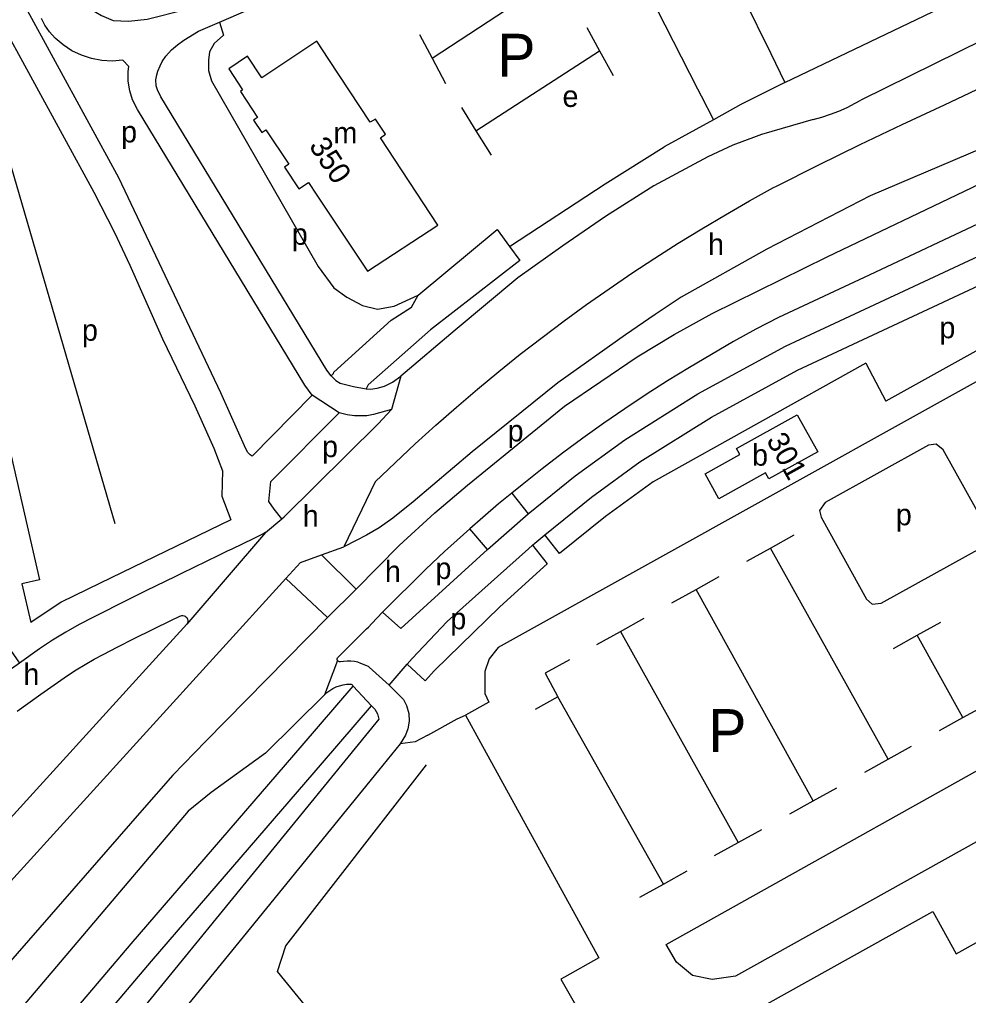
# Model space of a CAD drawing. Extents: x 155696 to 157795, y 382328 to 384028.
# Drawn here: x 157377.7 to 157554.8, y 382850.6 to 383032.8 of the extents above; entities that cross this region are included whole.
import ezdxf

# ---------------------------------------------------------------- set-up
doc = ezdxf.new("R2010")
doc.units = 0
for name, color, linetype in [('BLT_Basislijn', 7, 'Continuous'), ('BLT_Bebouwing', 7, 'Continuous'), ('BLT_Centroide', 7, 'Continuous'), ('BLT_Huisnummer', 7, 'Continuous'), ('BLT_Tekst_parkeren', 7, 'Continuous'), ('BLT_Vlakafsluiter', 7, 'Continuous')]:
    doc.layers.add(name, color=color, linetype=linetype)

msp = doc.modelspace()

# ---------------------------------------------------------------- linework, layer by layer
at = {"layer": 'BLT_Basislijn'}
for p, q in [((157494.61, 383073.77), (157517.91, 383026.39)), ((157415.02, 383032.25), (157467.68, 383055.02)), ((157454.71, 383025.53), (157477.42, 383040.42)), ((157483.6, 383031.25), (157485.99, 383026.89)), ((157452.34, 383029.97), (157454.71, 383025.53)), ((157557.58, 383028.97), (157534.73, 383017.71)), ((157462.91, 383011.99), (157485.99, 383026.89)), ((157485.99, 383026.89), (157488.49, 383022.31)), ((157454.71, 383025.53), (157457.23, 383020.82)), ((157517.91, 383026.39), (157520.56, 383021)), ((157504.26, 383019.84), (157504.94, 383018.5)), ((157504.94, 383018.5), (157507.21, 383014.04)), ((157460.21, 383016.36), (157462.91, 383011.99)), ((157507.21, 383014.04), (157498.04, 383008.97)), ((157462.91, 383011.99), (157465.74, 383007.42)), ((157614.42, 383003.23), (157539.42, 382961.52)), ((157535.66, 382968.63), (157539.42, 382961.52)), ((157437.39, 382959.36), (157432.33, 382962.67)), ((157469.59, 382944.37), (157472.66, 382940.49)), ((157417.15, 382939.38), (157392.8, 382927.56)), ((157423.62, 382937.01), (157426.68, 382939.55)), ((157465.05, 382933.83), (157472.66, 382940.49)), ((157465.05, 382933.83), (157461.76, 382937.7)), ((157517.86, 382934.13), (157522.28, 382936.59)), ((157417.34, 382933.92), (157416.47, 382933.52)), ((157466.91, 382928.79), (157472.72, 382933.99)), ((157513.45, 382931.68), (157517.86, 382934.13)), ((157539.83, 382894.73), (157517.86, 382934.13)), ((157416.47, 382933.52), (157414.84, 382932.71)), ((157434.08, 382932.85), (157440.54, 382926.43)), ((157448.86, 382919.12), (157465.05, 382933.83)), ((157406.8, 382928.8), (157401.27, 382926.11)), ((157427.45, 382928.46), (157435.21, 382921.17)), ((157453.58, 382930.2), (157445.47, 382922.13)), ((157503.99, 382926.41), (157508.29, 382928.8)), ((157378.15, 382927.46), (157379.82, 382920.22)), ((157435.21, 382921.17), (157440.54, 382926.43)), ((157499.46, 382923.89), (157503.99, 382926.41)), ((157525.84, 382886.94), (157503.99, 382926.41)), ((157448.86, 382919.12), (157445.47, 382922.13)), ((157489.89, 382918.58), (157494.3, 382921.04)), ((157545.25, 382917.85), (157549.68, 382920.3)), ((157485.47, 382916.12), (157489.89, 382918.58)), ((157489.89, 382918.58), (157511.86, 382879.17)), ((157540.83, 382915.38), (157545.25, 382917.85)), ((157553.8, 382902.49), (157545.25, 382917.85)), ((157446.72, 382908.55), (157450.07, 382912.44)), ((157443.38, 382904.67), (157439.96, 382908.36)), ((157497.9, 382871.42), (157478.21, 382906.38)), ((157553.8, 382902.49), (157558.23, 382904.95)), ((157549.41, 382900.05), (157553.8, 382902.49)), ((157539.83, 382894.73), (157544.22, 382897.17)), ((157535.45, 382892.29), (157539.83, 382894.73)), ((157444.71, 382892.6), (157420.82, 382863.27)), ((157525.84, 382886.94), (157530.26, 382889.4)), ((157521.46, 382884.5), (157525.84, 382886.94)), ((157511.86, 382879.17), (157516.27, 382881.62)), ((157507.45, 382876.73), (157511.86, 382879.17)), ((157497.9, 382871.42), (157502.31, 382873.87)), ((157493.49, 382868.97), (157497.9, 382871.42)), ((157420.82, 382863.27), (157405.37, 382844.32))]:
    msp.add_line(p, q, dxfattribs=at)
for points in [[(157520.56, 383021), (157562.54, 383041.14), (157551.22, 383097.51)], [(157380.3, 383067.07), (157386.53, 383040.89), (157387.15, 383039.27), (157388.11, 383037.73), (157389.35, 383036.18), (157390.88, 383034.74), (157393.04, 383033.48), (157395.19, 383032.6), (157398.04, 383032.43), (157401.52, 383032.82), (157408.43, 383034.54)], [(157419.95, 382952.63), (157415.29, 382963.08), (157396.28, 383003.23), (157378.55, 383035.65), (157376.74, 383038.57), (157375.07, 383040.82), (157372.83, 383043.32), (157371.22, 383044.91), (157369.71, 383046.26), (157368.44, 383047.46), (157366.29, 383049.8), (157365.05, 383051.54), (157362.88, 383055.34), (157361.11, 383060.1), (157359.75, 383066.24)], [(157467.68, 383055.02), (157483, 383061.57), (157504.26, 383019.84)], [(157395.59, 382938.62), (157375.14, 383008.82), (157371.59, 383024.1), (157368.87, 383027.72), (157354.54, 383041.57)], [(157373.81, 383033.02), (157391.58, 383000.53), (157395.47, 382993.02), (157398.28, 382986.9), (157404.38, 382973.19), (157410.42, 382960.66), (157414, 382952.76), (157415.6, 382948.55), (157415.49, 382943.8), (157417.15, 382939.38)], [(157432.33, 382962.67), (157430.94, 382964.53), (157399.73, 383015.93), (157398.82, 383017.76), (157398.29, 383019.47), (157398.01, 383021.24), (157398.02, 383023.04), (157398.13, 383024), (157397, 383025.15), (157395.04, 383024.99), (157393.08, 383025.11), (157391.15, 383025.46), (157389.29, 383026.1), (157387.51, 383026.92), (157385.88, 383028.02), (157384.37, 383029.27), (157383.29, 383030.46), (157382.42, 383031.71), (157381.81, 383032.97)], [(157411.11, 383030.56), (157415.02, 383032.25)], [(157415.02, 383032.25), (157415.77, 383029.81), (157414.04, 383028.25), (157413.17, 383026.7), (157413, 383025.14), (157413, 383023.23), (157413.52, 383021.33), (157433.43, 382986.68), (157436.38, 382982.7), (157438.8, 382980.96), (157441.74, 382979.4), (157444.52, 382978.71), (157447.63, 382979.23), (157452.14, 382981.31)], [(157435.91, 382966.23), (157435.09, 382967.33), (157404.11, 383018.34), (157403.48, 383019.62), (157403.25, 383020.35), (157403.13, 383021.47), (157403.35, 383022.45), (157403.55, 383023.13), (157403.94, 383024.11), (157404.34, 383024.9), (157405.04, 383025.94), (157406.07, 383027.11), (157407.19, 383028.05), (157408.38, 383028.9), (157411.11, 383030.56)], [(157440.54, 382926.43), (157448.6, 382934.6), (157455.22, 382940.72), (157461.35, 382945.88), (157479.41, 382960.62), (157493.01, 382969.83), (157499.89, 382973.99), (157506.97, 382977.92), (157528.46, 382988.47), (157555.5, 383001.43), (157568.48, 383007.62), (157581.01, 383013.6), (157596.88, 383021.11), (157612.01, 383027.85), (157619.48, 383031.88)], [(157519.01, 383001.67), (157526.79, 383005.57), (157534.61, 383009.4), (157542.47, 383013.16), (157550.36, 383016.84), (157559.95, 383021.36)], [(157520.56, 383021), (157512.36, 383016.9), (157507.21, 383014.04)], [(157525.83, 383014.08), (157527.46, 383014.54), (157529.05, 383015.07), (157530.62, 383015.68), (157532.17, 383016.36), (157533.67, 383017.12), (157534.73, 383017.71)], [(157525.83, 383014.08), (157516.17, 383011.3), (157515.22, 383010.94)], [(157515.22, 383010.94), (157510.85, 383009.29), (157506.15, 383007.1), (157496.13, 383001.74), (157487.06, 382995.98), (157479.14, 382990.53), (157470.72, 382984.57), (157459.05, 382974.77), (157448.89, 382966.19)], [(157355.14, 383007.28), (157362.88, 383009.06), (157381.48, 382928.22)], [(157469.15, 382990.42), (157487.04, 383002.11), (157498.04, 383008.97)], [(157475.78, 382936.58), (157484.46, 382943.64), (157493.46, 382950.18), (157506.87, 382958.57), (157522.92, 382967.33), (157614.05, 383009.86)], [(157557.24, 383008.7), (157536.48, 382999.85), (157517.18, 382989.89), (157501.2, 382980.96), (157496.37, 382977.68)], [(157444.11, 382946.47), (157447.82, 382950.05), (157451.58, 382953.57), (157455.39, 382957.03), (157459.26, 382960.43), (157463.18, 382963.78), (157467.15, 382967.06), (157471.18, 382970.28), (157475.25, 382973.43), (157479.37, 382976.52), (157483.54, 382979.55), (157487.75, 382982.52), (157492.01, 382985.41), (157496.31, 382988.24), (157500.66, 382991.01), (157505.05, 382993.7), (157509.48, 382996.33), (157513.95, 382998.89), (157518.46, 383001.38), (157519.01, 383001.67)], [(157472.66, 382940.49), (157481.41, 382947.6), (157490.66, 382954.33), (157504.34, 382962.89), (157520.66, 382971.8), (157575.24, 382997.26)], [(157558.75, 382995.6), (157536.26, 382985.07)], [(157452.14, 382981.31), (157466.87, 382993.54), (157469.15, 382990.42)], [(157469.15, 382990.42), (157471.08, 382987.81), (157454.42, 382974.84), (157442.81, 382964.61), (157442.4, 382963.81)], [(157599.1, 382988.99), (157467.08, 382915.57), (157465.35, 382913.45), (157464.56, 382911.11), (157464.56, 382908.86), (157464.56, 382907.01), (157465.29, 382905.34)], [(157536.26, 382985.07), (157519.38, 382977.17)], [(157435.91, 382966.23), (157436.34, 382966.72), (157436.39, 382966.95), (157447.08, 382976.66), (157450.9, 382979.1), (157452.14, 382981.31)], [(157496.37, 382977.68), (157490.82, 382973.9), (157478.16, 382964.98), (157462.18, 382952.1), (157451.18, 382942.76), (157447.37, 382939.7), (157444.84, 382937.91), (157442.46, 382936.52), (157440.57, 382935.5), (157438.24, 382934.36)], [(157519.38, 382977.17), (157515.16, 382974.94), (157510.98, 382972.64), (157506.84, 382970.27), (157502.73, 382967.84), (157498.67, 382965.33), (157494.65, 382962.76), (157490.68, 382960.12), (157486.75, 382957.41), (157482.87, 382954.64), (157479.03, 382951.8), (157475.24, 382948.9), (157471.5, 382945.94), (157469.59, 382944.37)], [(157535.66, 382968.63), (157495.98, 382946.46), (157487.1, 382940.02), (157478.5, 382933.13), (157475.78, 382936.58)], [(157435.91, 382966.23), (157436.76, 382965.37), (157437.54, 382964.91), (157440.02, 382964.25), (157442.4, 382963.81)], [(157442.4, 382963.81), (157443.2, 382963.75), (157444.48, 382963.95), (157445.82, 382964.34), (157447.31, 382965.07), (157448.89, 382966.19)], [(157432.33, 382962.67), (157421.14, 382951.26), (157420.75, 382951.54), (157420.34, 382951.98), (157419.95, 382952.63)], [(157426.68, 382939.55), (157427.12, 382939.92), (157444.65, 382957.32), (157447.15, 382959.99)], [(157447.15, 382959.99), (157443.76, 382959.04), (157442.51, 382958.82), (157441.61, 382958.77), (157440.24, 382958.8), (157438.89, 382958.98), (157437.39, 382959.36)], [(157426.68, 382939.55), (157425.23, 382941.37), (157424.24, 382942.81), (157424.64, 382946.54), (157437.39, 382959.36)], [(157469.59, 382944.37), (157467.13, 382942.35), (157464.18, 382939.82), (157461.76, 382937.7)], [(157461.76, 382937.7), (157460.59, 382936.67), (157457.06, 382933.47), (157453.58, 382930.2)], [(157423.62, 382937.01), (157423.32, 382936.83), (157421.33, 382935.86), (157417.34, 382933.92)], [(157473.44, 382934.63), (157473.92, 382935.06), (157475.78, 382936.58)], [(157434.08, 382932.85), (157438.24, 382934.36)], [(157473.44, 382934.63), (157476.21, 382931.15), (157467.33, 382923.15), (157455.16, 382911.27), (157453.44, 382909.33), (157450.07, 382912.44)], [(157472.72, 382933.99), (157473.44, 382934.63)], [(157414.84, 382932.71), (157407.93, 382929.35), (157406.8, 382928.8)], [(157430.15, 382931.42), (157434.08, 382932.85)], [(157427.45, 382928.46), (157430.15, 382931.42)], [(157253.63, 382724.61), (157366.67, 382857.64), (157375.4, 382871.21), (157427.45, 382928.46)], [(157450.07, 382912.44), (157450.99, 382913.52), (157457.56, 382920.42), (157466.91, 382928.79)], [(157381.48, 382928.22), (157378.15, 382927.46)], [(157392.8, 382927.56), (157385.52, 382924.03), (157379.82, 382920.22)], [(157401.27, 382926.11), (157398.18, 382924.61), (157391.43, 382921.19)], [(157435.21, 382921.17), (157412.48, 382898.08), (157406.33, 382891.74), (157400.57, 382885.12), (157334.47, 382809.42), (157258.65, 382720.15)], [(157391.43, 382921.19), (157388.86, 382919.86), (157386.34, 382918.44), (157383.87, 382916.92), (157381.47, 382915.31)], [(157406.07, 382920.66), (157407.41, 382921.31), (157407.64, 382921.43)], [(157407.64, 382921.43), (157407.82, 382921.5), (157408.01, 382921.54), (157408.22, 382921.55), (157408.43, 382921.5), (157408.62, 382921.42), (157408.79, 382921.31), (157408.92, 382921.17), (157409.03, 382921.01), (157409.1, 382920.82), (157409.14, 382920.62), (157409.14, 382920.41), (157409.09, 382920.18), (157408.94, 382919.91)], [(157445.47, 382922.13), (157443.48, 382920.06), (157442.84, 382919.38)], [(157408.94, 382919.91), (157402.56, 382912.86), (157373.4, 382880.9), (157343.68, 382856.3), (157301.48, 382806.92), (157282.32, 382784.63)], [(157395.93, 382915.61), (157399.12, 382917.25), (157406.07, 382920.66)], [(157437.07, 382913.16), (157437.03, 382913.3), (157437.03, 382913.47), (157437.07, 382913.61), (157437.17, 382913.75), (157442.5, 382919.02), (157442.84, 382919.38)], [(157375.37, 382917.26), (157374.77, 382916.86), (157377.72, 382912.64)], [(157381.47, 382915.31), (157377.72, 382912.64)], [(157386.65, 382910.32), (157388.29, 382911.37), (157389.95, 382912.39), (157391.64, 382913.36), (157393.35, 382914.28)], [(157393.35, 382914.28), (157395.93, 382915.61)], [(157377.72, 382912.64), (157376.24, 382911.58)], [(157443, 382911.89), (157442.84, 382912.03), (157441.44, 382912.6), (157440.83, 382912.8), (157440.21, 382912.95), (157439.54, 382913.03), (157438.87, 382913.04), (157438.19, 382912.98), (157437.6, 382912.87), (157437.44, 382912.87), (157437.32, 382912.92), (157437.18, 382913.01), (157437.07, 382913.16)], [(157480.37, 382913.28), (157475.8, 382910.75), (157478.21, 382906.38)], [(157377.31, 382903.66), (157381.72, 382906.85), (157386.65, 382910.32)], [(157446.72, 382908.55), (157443, 382911.89)], [(157593.84, 382906.04), (157594.24, 382904.17), (157594.13, 382902.61), (157593.57, 382901), (157592.56, 382899.54), (157514.71, 382856.12), (157511.33, 382854.24), (157506.99, 382853.61), (157503.31, 382854.36), (157500.31, 382856.87), (157498.4, 382860.15), (157576.49, 382903.81), (157588.99, 382910.77), (157589.61, 382911.05), (157590.36, 382911.11), (157591.12, 382910.88), (157591.82, 382910.26), (157592, 382910.02), (157593.03, 382908.12), (157593.84, 382906.04)], [(157434.63, 382906.74), (157435.07, 382907.15), (157435.62, 382907.56), (157436.17, 382907.9), (157436.84, 382908.22), (157437.43, 382908.44), (157438.11, 382908.61), (157438.73, 382908.71), (157439.44, 382908.75), (157439.61, 382908.72), (157439.75, 382908.65), (157439.85, 382908.56), (157439.92, 382908.46), (157439.96, 382908.36)], [(157446.72, 382908.55), (157449.36, 382905.85), (157449.97, 382904.76), (157450.37, 382903.26), (157450.46, 382901.82), (157450.21, 382900.41), (157449.75, 382899.2), (157448.79, 382897.61)], [(157434.63, 382906.74), (157423.6, 382895.87), (157413.48, 382888.5), (157409.2, 382885.05), (157298.01, 382753.93), (157263.65, 382713.32)], [(157282.65, 382707.97), (157284.29, 382711.23), (157284.11, 382713.16), (157284.81, 382718.11), (157286.73, 382722.26), (157290.23, 382727.09), (157361.51, 382816.65), (157398.57, 382860.25), (157430.45, 382897.3), (157439.96, 382908.36)], [(157465.29, 382905.34), (157460.93, 382902.94)], [(157478.21, 382906.38), (157473.97, 382904.01)], [(157294.15, 382723.98), (157365.38, 382813.47), (157402.37, 382857), (157434.24, 382894.04), (157443.38, 382904.67)], [(157443.38, 382904.67), (157444.01, 382904.08), (157444.55, 382903.17), (157444.75, 382902.2), (157397.86, 382844.71), (157395.53, 382841.42)], [(157453.93, 382899.23), (157459.41, 382902.28), (157460.93, 382902.94)], [(157460.93, 382902.94), (157463.77, 382897.83), (157485.85, 382857.62)], [(157500.55, 382842.07), (157501.52, 382840.28), (157548.2, 382866.27), (157552.51, 382858.39), (157578.68, 382872.96), (157611.59, 382891.3), (157607.18, 382899.1), (157606.48, 382900.41)], [(157448.79, 382897.61), (157444.71, 382892.6)], [(157453.93, 382899.23), (157451.59, 382897.93), (157448.79, 382897.61)], [(157446.54, 382823.9), (157434.97, 382843.99), (157425.84, 382855.08), (157427.42, 382859.92), (157453.65, 382893.65)], [(157479.42, 382854.06), (157478.75, 382853.69), (157482.7, 382846.69)]]:
    msp.add_lwpolyline(points, dxfattribs=at)
msp.add_lwpolyline([(157538.53, 382923.84), (157557.73, 382934.5), (157558.59, 382935.7), (157558.54, 382937.27), (157550.08, 382952.43), (157548.82, 382953.49), (157547.37, 382953.32), (157528.05, 382942.62), (157527.05, 382941.14), (157527.32, 382939.88), (157535.79, 382924.57), (157536.87, 382923.67)], close=True, dxfattribs=at)
at = {"layer": 'BLT_Bebouwing'}
for p, q in [((157442.68, 382985.78), (157455.77, 382994.36)), ((157485.85, 382857.62), (157479.42, 382854.06))]:
    msp.add_line(p, q, dxfattribs=at)
for points in [[(157455.77, 382994.36), (157445.07, 383010.65), (157446.02, 383011.34), (157444.13, 383014.16), (157443.15, 383013.58), (157435.44, 383025.32), (157433.23, 383028.69), (157422.93, 383021.9), (157420.27, 383025.93), (157416.78, 383023.55)], [(157416.78, 383023.55), (157419.33, 383019.62), (157418.94, 383019.29), (157422.15, 383014.48), (157421.39, 383013.98), (157422.94, 383011.65), (157423.71, 383012.16), (157427.96, 383005.77), (157427.15, 383005.22), (157429.82, 383001.15), (157431.63, 383002.33), (157433.2, 382999.98), (157442.68, 382985.78)]]:
    msp.add_lwpolyline(points, dxfattribs=at)
msp.add_lwpolyline([(157522.88, 382959.01), (157526.71, 382952.1), (157517.54, 382947.01), (157516.92, 382948.13), (157508.26, 382943.32), (157505.69, 382947.95), (157512.17, 382951.55), (157511.53, 382952.71)], close=True, dxfattribs=at)
at = {"layer": 'BLT_Vlakafsluiter'}
for p, q in [((157448.89, 382966.19), (157447.15, 382959.99)), ((157444.11, 382946.47), (157438.24, 382934.36)), ((157423.62, 382937.01), (157408.94, 382919.91)), ((157437.07, 382913.16), (157434.63, 382906.74))]:
    msp.add_line(p, q, dxfattribs=at)

# ---------------------------------------------------------------- texts
at = {"layer": 'BLT_Centroide'}
for s, p in [('e', (157479.06, 383016.44)), ('p', (157396.68, 383009.81)), ('m', (157436.31, 383009.62)), ('p', (157428.53, 382990.7)), ('h', (157506.22, 382988.81)), ('p', (157389.38, 382972.8)), ('p', (157549.4, 382973.27)), ('p', (157468.82, 382954.02)), ('p', (157434.19, 382951.08)), ('b', (157514.44, 382949.49)), ('h', (157430.58, 382938.14)), ('p', (157541.27, 382938.37)), ('h', (157445.92, 382927.76)), ('p', (157455.35, 382928.35)), ('p', (157458.13, 382918.96)), ('h', (157378.44, 382908.59))]:
    msp.add_text(s, height=4, dxfattribs=at).set_placement(p)
at = {"layer": 'BLT_Huisnummer'}
for s, rotation, p in [('350', 303.3783, (157431.63, 383009.17)), ('301', 299.0915, (157517.01, 382954.28))]:
    msp.add_text(s, height=4, rotation=rotation, dxfattribs=at).set_placement(p)
at = {"layer": 'BLT_Tekst_parkeren'}
for p in [(157466.88, 383022.09), (157506.25, 382896.06)]:
    msp.add_text('P', height=8, dxfattribs=at).set_placement(p)

doc.saveas('drawing.dxf')
